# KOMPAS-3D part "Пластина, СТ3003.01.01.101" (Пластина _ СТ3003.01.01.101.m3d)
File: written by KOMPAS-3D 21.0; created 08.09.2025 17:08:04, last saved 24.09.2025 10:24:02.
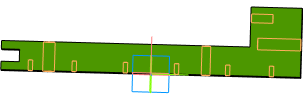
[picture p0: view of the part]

Document properties: Полное имя файла: C:\Users\1\Yandex.Disk\Документы\Новая папка\Стапель №2\Стапель _ СТ3003.00.00.000\Опора _ СТ3003.01.00.000\3D\Кронштейн _ СТ3003.01.01.000\Основание _ СТ3003.01.01.100\Пластина _ СТ3003.01.01.101.m3d

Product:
- Part/product: Пластина  | designation СТ3003.01.01.101
    Материал: Лист$dБ-ПН-НО-25 ГОСТ 19903-2015;Ст3сп ГОСТ 14637-89$ (density 7850 kg/m3)
    Масса: 3.643787
    Форматы листов документа: A2

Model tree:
1. Эскиз:1
2. Элемент выдавливания:1
     Расстояние 1 = 25
3. Эскиз:81  (with: Элемент выдавливания:1)
4. ЛСК:56  (with: Плоскость XY, Плоскость ZX, Плоскость ZY, Ось X, Ось Y, Ось Z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)
     Ось X. X = -1; Ось Y. Y = 1; Ось Z. Z = -1; Координата Y = -165; Точка начала. Y = -165
5. Эскиз:82
6. Элемент вращения:19
     Угол 1 = 360
7. Смещенная плоскость:18  (with: Элемент выдавливания:1)
     Расстояние = 0.458734
8. Условное изображение резьбы:20  (with: Элемент вращения:19)  (labels: 6x1)
     Длина резьбы = 14.5413; Шаг резьбы = 1; Номинальный диаметр резьбы = 6
9. Подгонка:1
10. Отверстие М6x15-20/1x45°
11. Эскиз:84  (with: Элемент выдавливания:1)
12. ЛСК:58  (with: Плоскость XY, Плоскость ZX, Плоскость ZY, Ось X, Ось Y, Ось Z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)
     Ось X. X = -1; Ось Y. Y = 1; Ось Z. Z = -1; Координата Y = -105; Точка начала. Y = -105
13. Эскиз:85
14. Элемент вращения:20
     Угол 1 = 360
15. Смещенная плоскость:19  (with: Элемент выдавливания:1)
     Расстояние = 0.458734
16. Условное изображение резьбы:21  (with: Элемент вращения:20)  (labels: 6x1)
     Длина резьбы = 14.5413; Шаг резьбы = 1; Номинальный диаметр резьбы = 6
17. Подгонка:2
18. Отверстие М6x15-20/1x45° (1)
19. Эскиз:87  (with: Элемент выдавливания:1)
20. ЛСК:60  (with: Плоскость XY, Плоскость ZX, Плоскость ZY, Ось X, Ось Y, Ось Z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)
     Ось X. X = -1; Ось Y. Y = 1; Ось Z. Z = -1; Координата Y = -35; Точка начала. Y = -35
21. Эскиз:88
22. Элемент вращения:21
     Угол 1 = 360
23. Смещенная плоскость:20  (with: Элемент выдавливания:1)
     Расстояние = 0.458734
24. Условное изображение резьбы:22  (with: Элемент вращения:21)  (labels: 6x1)
     Длина резьбы = 14.5413; Шаг резьбы = 1; Номинальный диаметр резьбы = 6
25. Подгонка:3
26. Отверстие М6x15-20/1x45° (2)
27. Эскиз:90  (with: Элемент выдавливания:1)
28. ЛСК:62  (with: Плоскость XY, Плоскость ZX, Плоскость ZY, Ось X, Ось Y, Ось Z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)
     Ось X. X = -1; Ось Y. Y = 1; Ось Z. Z = -1; Координата Y = 35; Точка начала. Y = 35
29. Эскиз:91
30. Элемент вращения:22
     Угол 1 = 360
31. Смещенная плоскость:21  (with: Элемент выдавливания:1)
     Расстояние = 0.458734
32. Условное изображение резьбы:23  (with: Элемент вращения:22)  (labels: 6x1)
     Длина резьбы = 14.5413; Шаг резьбы = 1; Номинальный диаметр резьбы = 6
33. Подгонка:4
34. Отверстие М6x15-20/1x45° (3)
35. Эскиз:93  (with: Элемент выдавливания:1)
36. ЛСК:64  (with: Плоскость XY, Плоскость ZX, Плоскость ZY, Ось X, Ось Y, Ось Z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)
     Ось X. X = -1; Ось Y. Y = 1; Ось Z. Z = -1; Координата Y = 105; Точка начала. Y = 105
37. Эскиз:94
38. Элемент вращения:23
     Угол 1 = 360
39. Смещенная плоскость:22  (with: Элемент выдавливания:1)
     Расстояние = 0.458734
40. Условное изображение резьбы:24  (with: Элемент вращения:23)  (labels: 6x1)
     Длина резьбы = 14.5413; Шаг резьбы = 1; Номинальный диаметр резьбы = 6
41. Подгонка:5
42. Отверстие М6x15-20/1x45° (4)
43. Эскиз:96  (with: Элемент выдавливания:1)
44. ЛСК:66  (with: Плоскость XY, Плоскость ZX, Плоскость ZY, Ось X, Ось Y, Ось Z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)
     Ось X. X = -1; Ось Y. Y = 1; Ось Z. Z = -1; Координата Y = 165; Точка начала. Y = 165
45. Эскиз:97
46. Элемент вращения:24
     Угол 1 = 360
47. Смещенная плоскость:23  (with: Элемент выдавливания:1)
     Расстояние = 0.458734
48. Условное изображение резьбы:25  (with: Элемент вращения:24)  (labels: 6x1)
     Длина резьбы = 14.5413; Шаг резьбы = 1; Номинальный диаметр резьбы = 6
49. Подгонка:6
50. Отверстие М6x15-20/1x45° (5)
51. Эскиз:78  (with: Элемент выдавливания:1)
52. ЛСК:54  (with: Плоскость XY, Плоскость ZX, Плоскость ZY, Ось X, Ось Y, Ось Z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)
     Ось X. Y = 1; Ось Y. X = 1; Ось Z. Z = -1; Координата X = 45; Координата Y = 205; Точка начала. Х = 45; Точка начала. Y = 205
53. Эскиз:79
54. Элемент вращения:18
     Угол 1 = 360
55. Смещенная плоскость:17  (with: Элемент выдавливания:1)
     Расстояние = 0.917468
56. Условное изображение резьбы:19  (with: Элемент вращения:18, Подгонка:1)  (labels: 16x2)
     Длина резьбы = 59.0825; Шаг резьбы = 2; Номинальный диаметр резьбы = 16
57. Отверстие М16x60/2x45°
58. Эскиз:62  (with: Элемент выдавливания:1)
59. Элемент выдавливания:5
60. Условное изображение резьбы:14  (with: Элемент выдавливания:5, Подгонка:2)  (labels: M16; cil0_24705-2004 coarse)
     Длина резьбы = 40; Шаг резьбы = 2; Номинальный диаметр резьбы = 16
61. Условное изображение резьбы:15  (with: Элемент выдавливания:5, Подгонка:3)  (labels: M12; cil0_24705-2004 coarse)
     Длина резьбы = 40; Шаг резьбы = 1.75; Номинальный диаметр резьбы = 12
62. Фаска:1  (with: Элемент выдавливания:5)
     Угол = 45; Длина 1 = 2; Длина 2 = 2
63. Фаска:2  (with: Элемент выдавливания:5)
     Угол = 45; Длина 1 = 1.6; Длина 2 = 1.6
64. Эскиз:75  (with: Элемент выдавливания:1)
65. ЛСК:52  (with: Плоскость XY, Плоскость ZX, Плоскость ZY, Ось X, Ось Y, Ось Z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)
     Ось X. Y = -1; Ось Y. X = 1; Ось Z. Z = 1; Координата X = 80; Координата Y = 135; Точка начала. Х = 80; Точка начала. Y = 135
66. Эскиз:76
67. Элемент вращения:17
     Угол 1 = 360
68. Смещенная плоскость:16  (with: Элемент выдавливания:1)
     Расстояние = 0.652785
69. Условное изображение резьбы:18  (with: Элемент вращения:17, Подгонка:6)  (labels: 12x1,75)
     Длина резьбы = 29.3472; Шаг резьбы = 1.75; Номинальный диаметр резьбы = 12
70. Отверстие М12x30-35/1,6x45°
71. Эскиз:71  (with: Элемент выдавливания:1)
72. ЛСК:49  (with: Плоскость XY, Плоскость ZX, Плоскость ZY, Ось X, Ось Y, Ось Z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)
     Ось X. X = 1; Ось Y. Y = 1; Ось Z. Z = 1; Координата X = 95; Координата Y = 190; Точка начала. Х = 95; Точка начала. Y = 190
73. Эскиз:72
74. Присоединительная точка:1
     Перенос X = -10; Расстояние = -10
75. Элемент вращения:16
     Угол 1 = 360
76. Отверстие Ф16x35/2x45°  (labels: Лист$dБ-ПН-НО-25 ГОСТ 19903-2015;Ст3сп ГОСТ 14637-89$)

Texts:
  KTE.LIST=f.sO0tLtictm5WUlIlwVlc
  KTE.LIST=LTWD36N5dmSErgwNQxupvb
  Edge1
  Edge2
  СТ3003.01.01.101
